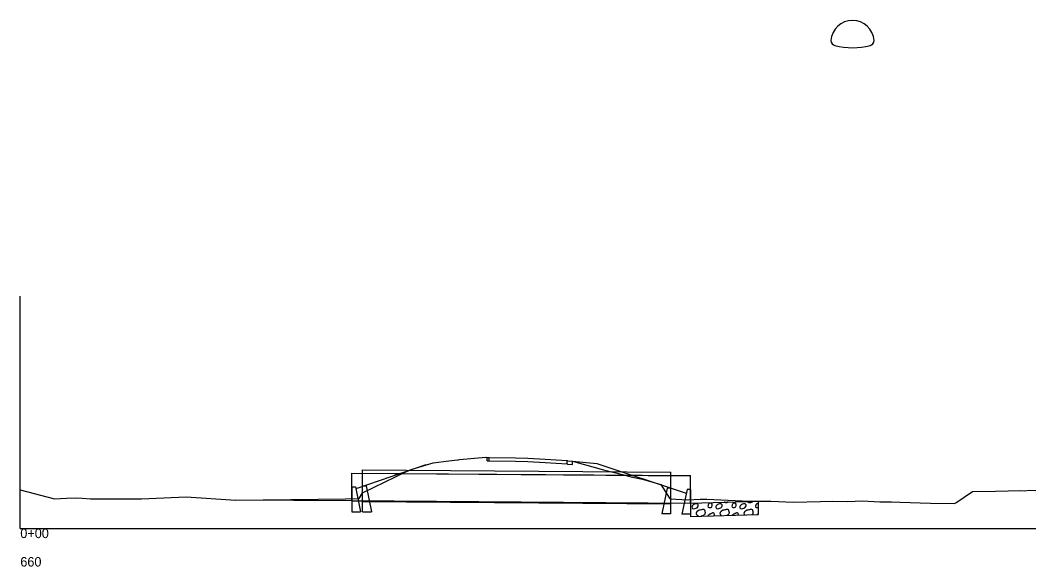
# Model space of a CAD drawing. Extents: x 153902 to 157473, y 413085 to 414252.
# Drawn here: x 155453.1 to 155753.1, y 413791.9 to 413953.3 of the extents above; entities that cross this region are included whole.
import ezdxf

# ---------------------------------------------------------------- set-up
doc = ezdxf.new("R2010")
doc.units = 0
for name, color, linetype in [('Default', 7, 'Continuous'), ('DR_X_Ditch', 7, 'Continuous'), ('DR_X_Headwall', 7, 'Continuous'), ('PV_X_Driveway', 7, 'Continuous'), ('RD_X_Cells', 7, 'Continuous'), ('RW_X_Esmt_SH', 7, 'Continuous'), ('UT_X_Misc_Cells', 7, 'Continuous')]:
    doc.layers.add(name, color=color, linetype=linetype)

msp = doc.modelspace()

# ---------------------------------------------------------------- linework, layer by layer
at = {"layer": 'Default'}
for q in [(155453.1, 413871.82), (155753.1, 413803.18)]:
    msp.add_line((155453.1, 413803.18), q, dxfattribs=at)
at = {"layer": 'DR_X_Ditch'}
for p, q in [((155554.24, 413808.18), (155554.24, 413820.56)), ((155554.24, 413820.56), (155645.26, 413819.88)), ((155645.26, 413807.5), (155645.26, 413819.88)), ((155554.24, 413815.85), (155555.24, 413815.85)), ((155555.24, 413815.85), (155556.82, 413808.18)), ((155644.26, 413815.17), (155642.68, 413807.5)), ((155645.26, 413815.17), (155644.26, 413815.17)), ((155554.24, 413811.14), (155645.26, 413810.46)), ((155554.24, 413808.18), (155556.82, 413808.18)), ((155645.26, 413807.5), (155642.68, 413807.5))]:
    msp.add_line(p, q, dxfattribs=at)
at = {"layer": 'DR_X_Headwall'}
for p, q in [((155651.1, 413810.71), (155671.1, 413811.3)), ((155671.1, 413811.3), (155671.1, 413807.3)), ((155651.1, 413807.42), (155651.1, 413806.71)), ((155651.1, 413806.71), (155671.1, 413807.3))]:
    msp.add_line(p, q, dxfattribs=at)
for points, degree in [([(155662.29, 413811.04), (155661.94, 413810.81), (155661.5, 413810.74), (155661.16, 413810.94), (155661.12, 413810.96), (155661.09, 413810.98), (155661.06, 413811)], 3), ([(155669.63, 413811.26), (155669.6, 413811.22), (155669.56, 413811.19), (155669.53, 413811.16), (155669.15, 413810.84), (155668.62, 413810.71), (155668.23, 413810.94), (155668.1, 413811.01), (155667.98, 413811.1), (155667.86, 413811.21)], 3), ([(155653.59, 413806.78), (155653.53, 413806.79), (155653.48, 413806.81), (155653.43, 413806.83), (155653.26, 413806.91), (155653.13, 413807.03), (155653.03, 413807.19), (155652.86, 413807.46), (155652.8, 413807.83), (155652.96, 413808.08), (155653.06, 413808.25), (155653.19, 413808.4), (155653.37, 413808.51), (155653.51, 413808.6), (155653.65, 413808.69), (155653.82, 413808.72), (155653.87, 413808.73), (155653.93, 413808.75), (155653.98, 413808.76)], 3), ([(155653.97, 413808.75), (155654.27, 413808.81), (155654.57, 413808.86), (155654.87, 413808.91), (155655.18, 413808.95), (155655.32, 413808.43), (155655.39, 413808.15), (155655.46, 413807.89), (155655.42, 413807.57), (155655.2, 413807.33), (155654.93, 413807.04), (155654.64, 413806.92), (155654.31, 413806.83), (155654.27, 413806.82), (155654.24, 413806.81), (155654.2, 413806.8)], 3), ([(155660.27, 413806.98), (155660.21, 413807.04), (155660.15, 413807.11), (155660.1, 413807.19), (155659.93, 413807.46), (155659.88, 413807.83), (155660.03, 413808.08), (155660.13, 413808.25), (155660.26, 413808.4), (155660.44, 413808.51), (155660.58, 413808.6), (155660.73, 413808.69), (155660.89, 413808.72), (155660.94, 413808.73), (155661, 413808.75), (155661.05, 413808.76)], 3), ([(155661.04, 413808.75), (155661.34, 413808.81), (155661.64, 413808.86), (155661.95, 413808.91), (155662.25, 413808.95), (155662.39, 413808.43), (155662.46, 413808.15), (155662.53, 413807.89), (155662.49, 413807.57), (155662.27, 413807.33), (155662.15, 413807.2), (155662.02, 413807.1), (155661.89, 413807.03)], 3), ([(155667.18, 413807.18), (155667.17, 413807.19), (155667.17, 413807.19), (155667.17, 413807.19), (155667, 413807.46), (155666.95, 413807.83), (155667.1, 413808.08), (155667.2, 413808.25), (155667.33, 413808.4), (155667.51, 413808.51), (155667.66, 413808.6), (155667.8, 413808.69), (155667.96, 413808.72), (155668.02, 413808.73), (155668.07, 413808.75), (155668.13, 413808.76)], 3), ([(155668.11, 413808.75), (155668.41, 413808.81), (155668.71, 413808.86), (155669.02, 413808.91), (155669.32, 413808.95), (155669.46, 413808.43), (155669.54, 413808.15), (155669.6, 413807.89), (155669.56, 413807.57), (155669.34, 413807.33), (155669.31, 413807.3), (155669.29, 413807.27), (155669.26, 413807.25)], 3), ([(155671.1, 413809.37), (155670.87, 413809.29), (155670.55, 413809.34), (155670.45, 413809.55), (155670.37, 413809.7), (155670.41, 413809.88), (155670.46, 413810.04), (155670.49, 413810.15), (155670.5, 413810.27), (155670.57, 413810.36), (155670.63, 413810.43), (155670.68, 413810.5), (155670.73, 413810.57)], 3), ([(155670.73, 413810.57), (155670.86, 413810.58), (155670.98, 413810.6), (155671.1, 413810.62)], 2), ([(155656.35, 413806.86), (155656.39, 413807.04), (155656.47, 413807.25), (155656.63, 413807.35), (155656.75, 413807.43), (155656.87, 413807.51), (155657, 413807.59)], 3), ([(155657, 413807.59), (155657.23, 413807.69), (155657.47, 413807.79), (155657.7, 413807.89), (155657.94, 413808), (155658.06, 413807.46), (155658.12, 413807.21), (155658.14, 413807.12), (155658.14, 413807.02), (155658.13, 413806.92)], 3), ([(155663.49, 413807.08), (155663.54, 413807.19), (155663.61, 413807.29), (155663.7, 413807.35), (155663.82, 413807.43), (155663.95, 413807.51), (155664.07, 413807.59)], 3), ([(155664.07, 413807.59), (155664.3, 413807.69), (155664.54, 413807.79), (155664.77, 413807.89), (155665.02, 413808), (155665.13, 413807.46), (155665.19, 413807.21), (155665.19, 413807.19), (155665.2, 413807.16), (155665.2, 413807.13)], 3), ([(155670.7, 413807.29), (155670.72, 413807.31), (155670.75, 413807.33), (155670.77, 413807.35), (155670.88, 413807.42), (155670.99, 413807.49), (155671.1, 413807.56)], 3)]:
    msp.add_open_spline(points, degree=degree, dxfattribs=at)
for points in [[(155651.79, 413810.13), (155652.29, 413810.38), (155652.89, 413810.5), (155653.32, 413810.34), (155653.38, 413809.93), (155653.04, 413809.34), (155652.42, 413809.1), (155651.71, 413809.11), (155651.54, 413809.54), (155651.64, 413809.94), (155651.79, 413810.13)], [(155656.59, 413810.57), (155657.35, 413810.68), (155657.56, 413810.02), (155657.08, 413809.43), (155656.31, 413809.55), (155656.31, 413810.04), (155656.43, 413810.36), (155656.59, 413810.57)], [(155658.86, 413810.13), (155659.36, 413810.38), (155659.97, 413810.5), (155660.39, 413810.34), (155660.46, 413809.93), (155660.11, 413809.34), (155659.49, 413809.1), (155658.78, 413809.11), (155658.61, 413809.54), (155658.72, 413809.94), (155658.86, 413810.13)], [(155663.66, 413810.57), (155664.42, 413810.68), (155664.63, 413810.02), (155664.15, 413809.43), (155663.38, 413809.55), (155663.38, 413810.04), (155663.5, 413810.36), (155663.66, 413810.57)], [(155665.94, 413810.13), (155666.44, 413810.38), (155667.04, 413810.5), (155667.46, 413810.34), (155667.53, 413809.93), (155667.19, 413809.34), (155666.56, 413809.1), (155665.86, 413809.11), (155665.68, 413809.54), (155665.79, 413809.94), (155665.94, 413810.13)]]:
    msp.add_spline(points, degree=3, dxfattribs=at)
at = {"layer": 'PV_X_Driveway'}
for p, q in [((155692.63, 413947.27), (155692.62, 413947.27)), ((155551.1, 413811.41), (155551.1, 413819.58)), ((155551.1, 413819.58), (155651.1, 413818.83)), ((155551.1, 413819.54), (155651.1, 413818.79)), ((155651.1, 413810.67), (155651.1, 413818.83)), ((155551.1, 413815.5), (155552.1, 413815.5)), ((155551.1, 413815.5), (155551.1, 413808.16)), ((155552.1, 413815.5), (155553.6, 413808.16)), ((155650.1, 413814.75), (155648.6, 413807.42)), ((155651.1, 413814.75), (155650.1, 413814.75)), ((155651.1, 413814.75), (155651.1, 413807.42)), ((155551.1, 413811.46), (155651.1, 413810.71)), ((155551.1, 413811.41), (155651.1, 413810.67)), ((155551.1, 413808.16), (155553.6, 413808.16)), ((155651.1, 413807.42), (155648.6, 413807.42))]:
    msp.add_line(p, q, dxfattribs=at)
for centre, radius, start, end in [((155698.98, 413946.88), 6.37, 3.4801, 176.5199), ((155694.12, 413947.27), 1.5, 180, 257.5397), ((155703.84, 413947.27), 1.5, 282.4603, 0), ((155698.98, 413966.62), 21.45, 255.7917, 284.2083)]:
    msp.add_arc(centre, radius, start, end, dxfattribs=at)
at = {"layer": 'RD_X_Cells'}
for p, q in [((155591.06, 413823.22), (155591.06, 413824.22)), ((155591.59, 413823.22), (155591.59, 413824.22)), ((155614.63, 413822.26), (155614.63, 413823.26)), ((155616.2, 413822.08), (155616.2, 413823.08))]:
    msp.add_line(p, q, dxfattribs=at)
msp.add_lwpolyline([(155591.06, 413823.22), (155591.59, 413823.22), (155599.38, 413823.06), (155603.1, 413822.98), (155608.19, 413822.69), (155614.63, 413822.26), (155614.79, 413822.24), (155616.2, 413822.08), (155616.2, 413822.08)], dxfattribs=at)
at = {"layer": 'RW_X_Esmt_SH'}
msp.add_lwpolyline([(155453.1, 413814.6), (155463.16, 413812), (155466.76, 413812.16), (155469.28, 413812.24), (155471.41, 413812.16), (155473.86, 413812.02), (155488.93, 413811.96), (155502.12, 413812.61), (155516.8, 413811.6), (155549.16, 413811.99), (155553.19, 413812.05), (155554.24, 413813.74), (155567.2, 413820), (155568.58, 413820.66), (155568.58, 413820.66), (155568.59, 413820.66), (155568.9, 413820.76), (155575.09, 413822.64), (155579.73, 413823.21), (155582.26, 413823.52), (155582.29, 413823.52), (155582.34, 413823.53), (155582.44, 413823.53), (155582.9, 413823.58), (155590.6, 413824.23), (155590.64, 413824.23), (155590.86, 413824.22), (155591.59, 413824.22), (155599.38, 413824.06), (155603.1, 413823.98), (155608.19, 413823.69), (155614.63, 413823.26), (155614.79, 413823.24), (155616.2, 413823.08), (155617.64, 413822.7), (155622.26, 413821.41), (155625.37, 413820.53), (155626.59, 413820.21), (155627.29, 413820.02), (155628.3, 413819.83), (155634, 413818.38), (155636.94, 413817.78), (155642.39, 413816.19), (155644.86, 413812.14), (155645.1, 413811.94), (155650.22, 413811.72), (155654.04, 413811.88), (155655.43, 413811.87), (155655.96, 413811.84), (155666.36, 413811.36), (155669.61, 413811.31), (155674.75, 413811.27), (155674.83, 413811.28), (155681.53, 413810.99), (155689.52, 413811.14), (155692.93, 413811.26), (155697.57, 413811.15), (155701.93, 413811.42), (155707.01, 413811.1), (155710.47, 413811.09), (155712.97, 413811.01), (155722.01, 413810.65), (155729.03, 413810.55), (155729.55, 413810.82), (155734.39, 413814.1), (155741.26, 413814.24), (155748.71, 413814.48), (155749.69, 413814.36), (155751.36, 413814.5), (155753.1, 413814.47)], dxfattribs=at)
at = {"layer": 'UT_X_Misc_Cells'}
for p, q in [((155616.2, 413823.08), (155623.43, 413822.43)), ((155572.87, 413821.97), (155552.21, 413814.94)), ((155623.43, 413822.43), (155649.87, 413813.64)), ((155551.1, 413811.41), (155516.8, 413811.6))]:
    msp.add_line(p, q, dxfattribs=at)

# ---------------------------------------------------------------- texts
at = {"layer": 'Default'}
for s, p in [('0+00', (155453.1, 413800.38)), ('660', (155453.1, 413791.98))]:
    msp.add_text(s, height=2.8, dxfattribs=at).set_placement(p)

doc.saveas('drawing.dxf')
